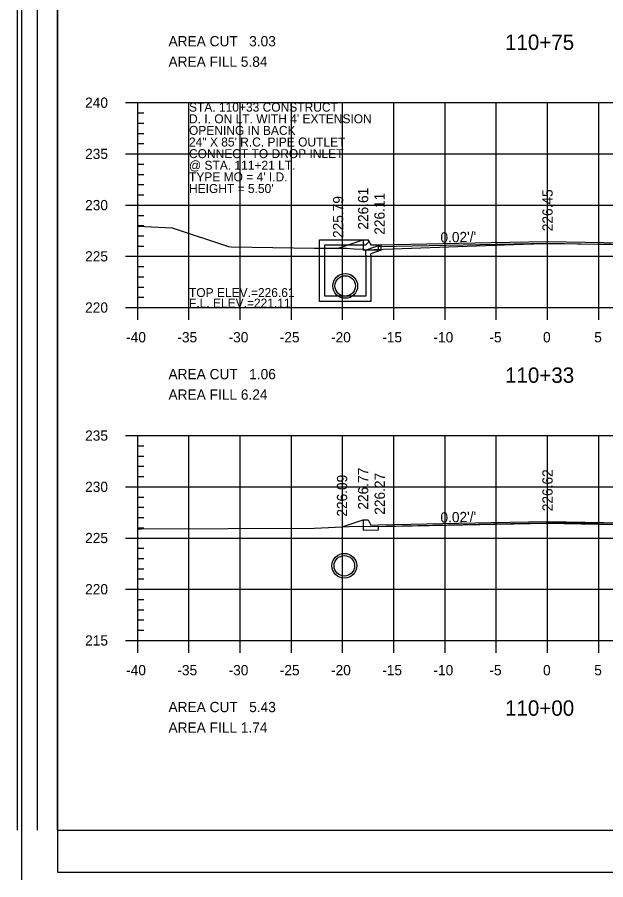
# Model space of a CAD drawing. Extents: x 1367903 to 1373764, y 376865 to 382130.
# Drawn here: x 1372354.5 to 1372469.4, y 377279.1 to 377447.5 of the extents above; entities that cross this region are included whole.
import ezdxf

# ---------------------------------------------------------------- set-up
doc = ezdxf.new("R2010")
doc.units = 0
for name, color, linetype in [('R_Axis', 7, 'Continuous'), ('R_Axis Annot', 7, 'Continuous'), ('R_Border', 7, 'Continuous'), ('R_Border PE', 7, 'Continuous'), ('R_Draft', 7, 'Continuous'), ('R_Exist Surface', 7, 'Continuous'), ('R_Fin Surface', 7, 'Continuous'), ('R_Fin Surface Annot', 7, 'Continuous'), ('R_Grid', 7, 'Continuous'), ('R_Water', 7, 'Continuous'), ('R_Water Annot', 7, 'Continuous')]:
    doc.layers.add(name, color=color, linetype=linetype)

msp = doc.modelspace()

# ---------------------------------------------------------------- linework, layer by layer
for p, q in [((1372413.54, 377404.05), (1372423.04, 377404.05)), ((1372413.54, 377401.05), (1372413.54, 377404.05)), ((1372423.21, 377403.72), (1372423.04, 377404.05)), ((1372414.54, 377401.05), (1372414.54, 377403.05)), ((1372414.54, 377403.05), (1372422.54, 377403.05)), ((1372423.21, 377403.72), (1372422.54, 377403.05)), ((1372425.54, 377403.09), (1372422.54, 377402.05)), ((1372422.54, 377401.05), (1372422.54, 377402.05)), ((1372425.54, 377402.03), (1372423.54, 377401.34)), ((1372423.54, 377401.05), (1372423.54, 377401.34))]:
    msp.add_line(p, q)
for points in [[(1372422.04, 377404.05), (1372422.04, 377403.38), (1372422.04, 377403.38), (1372422.04, 377402.02), (1372425.04, 377402.08), (1372425.04, 377402.74), (1372458.04, 377403.4), (1372491.04, 377402.74), (1372491.04, 377402.08), (1372494.04, 377402.02), (1372494.04, 377403.46), (1372508.04, 377403.74), (1372508.04, 377404.33)], [(1372425.54, 377402.03), (1372425.54, 377403.09)], [(1372422.04, 377349.38), (1372422.04, 377348.71), (1372422.04, 377348.71), (1372422.04, 377347.35), (1372425.04, 377347.41), (1372425.04, 377348.08), (1372458.04, 377348.74), (1372491.04, 377348.08), (1372491.04, 377347.41), (1372494.04, 377347.35), (1372494.04, 377348.79), (1372508.04, 377349.07), (1372508.04, 377349.66)]]:
    msp.add_lwpolyline(points)
at = {"layer": 'R_Axis'}
for p, q in [((1372375.64, 377430.84), (1372380.44, 377430.84)), ((1372378.04, 377390.84), (1372378.04, 377430.84)), ((1372378.04, 377428.84), (1372379.24, 377428.84)), ((1372378.04, 377426.84), (1372379.24, 377426.84)), ((1372378.04, 377424.84), (1372379.24, 377424.84)), ((1372378.04, 377422.84), (1372379.24, 377422.84)), ((1372375.64, 377420.84), (1372380.44, 377420.84)), ((1372378.04, 377418.84), (1372379.24, 377418.84)), ((1372378.04, 377416.84), (1372379.24, 377416.84)), ((1372378.04, 377414.84), (1372379.24, 377414.84)), ((1372378.04, 377412.84), (1372379.24, 377412.84)), ((1372375.64, 377410.84), (1372380.44, 377410.84)), ((1372378.04, 377408.84), (1372379.24, 377408.84)), ((1372378.04, 377406.84), (1372379.24, 377406.84)), ((1372378.04, 377404.84), (1372379.24, 377404.84)), ((1372378.04, 377402.84), (1372379.24, 377402.84)), ((1372375.64, 377400.84), (1372380.44, 377400.84)), ((1372378.04, 377398.84), (1372379.24, 377398.84)), ((1372378.04, 377396.84), (1372379.24, 377396.84)), ((1372378.04, 377394.84), (1372379.24, 377394.84)), ((1372378.04, 377388.44), (1372378.04, 377393.24)), ((1372378.04, 377392.84), (1372379.24, 377392.84)), ((1372388.04, 377388.44), (1372388.04, 377393.24)), ((1372398.04, 377388.44), (1372398.04, 377393.24)), ((1372408.04, 377388.44), (1372408.04, 377393.24)), ((1372418.04, 377388.44), (1372418.04, 377393.24)), ((1372428.04, 377388.44), (1372428.04, 377393.24)), ((1372438.04, 377388.44), (1372438.04, 377393.24)), ((1372448.04, 377388.44), (1372448.04, 377393.24)), ((1372458.04, 377388.44), (1372458.04, 377393.24)), ((1372468.04, 377388.44), (1372468.04, 377393.24)), ((1372375.64, 377390.84), (1372380.44, 377390.84)), ((1372378.04, 377390.84), (1372538.04, 377390.84)), ((1372375.64, 377365.84), (1372380.44, 377365.84)), ((1372378.04, 377325.84), (1372378.04, 377365.84)), ((1372378.04, 377363.84), (1372379.24, 377363.84)), ((1372378.04, 377361.84), (1372379.24, 377361.84)), ((1372378.04, 377359.84), (1372379.24, 377359.84)), ((1372378.04, 377357.84), (1372379.24, 377357.84)), ((1372375.64, 377355.84), (1372380.44, 377355.84)), ((1372378.04, 377353.84), (1372379.24, 377353.84)), ((1372378.04, 377351.84), (1372379.24, 377351.84)), ((1372378.04, 377349.84), (1372379.24, 377349.84)), ((1372378.04, 377347.84), (1372379.24, 377347.84)), ((1372375.64, 377345.84), (1372380.44, 377345.84)), ((1372378.04, 377343.84), (1372379.24, 377343.84)), ((1372378.04, 377341.84), (1372379.24, 377341.84)), ((1372378.04, 377339.84), (1372379.24, 377339.84)), ((1372378.04, 377337.84), (1372379.24, 377337.84)), ((1372375.64, 377335.84), (1372380.44, 377335.84)), ((1372378.04, 377333.84), (1372379.24, 377333.84)), ((1372378.04, 377331.84), (1372379.24, 377331.84)), ((1372378.04, 377329.84), (1372379.24, 377329.84)), ((1372378.04, 377323.44), (1372378.04, 377328.24)), ((1372388.04, 377323.44), (1372388.04, 377328.24)), ((1372398.04, 377323.44), (1372398.04, 377328.24)), ((1372408.04, 377323.44), (1372408.04, 377328.24)), ((1372418.04, 377323.44), (1372418.04, 377328.24)), ((1372428.04, 377323.44), (1372428.04, 377328.24)), ((1372438.04, 377323.44), (1372438.04, 377328.24)), ((1372448.04, 377323.44), (1372448.04, 377328.24)), ((1372458.04, 377323.44), (1372458.04, 377328.24)), ((1372468.04, 377323.44), (1372468.04, 377328.24)), ((1372378.04, 377327.84), (1372379.24, 377327.84)), ((1372375.64, 377325.84), (1372380.44, 377325.84)), ((1372378.04, 377325.84), (1372538.04, 377325.84))]:
    msp.add_line(p, q, dxfattribs=at)
at = {"layer": 'R_Border'}
for p, q in [((1372355.31, 377620.35), (1372355.31, 377279.12)), ((1372362.34, 377611.47), (1372362.34, 377280.59)), ((1372362.34, 377280.59), (1372566.67, 377280.59))]:
    msp.add_line(p, q, dxfattribs=at)
at = {"layer": 'R_Border PE'}
for p, q in [((1372354.51, 377610.76), (1372354.51, 377288.8)), ((1372358.42, 377610.76), (1372358.42, 377288.8)), ((1372362.34, 377288.8), (1372362.34, 377603.25)), ((1372362.34, 377288.8), (1372566.67, 377288.8))]:
    msp.add_line(p, q, dxfattribs=at)
at = {"layer": 'R_Exist Surface'}
for points in [[(1372378.04, 377406.7), (1372384.74, 377406.38), (1372384.83, 377406.37), (1372384.94, 377406.34), (1372395.78, 377402.74), (1372396.26, 377402.72), (1372412.53, 377402.42), (1372418.78, 377402.42), (1372420.3, 377402.28), (1372422.16, 377402.21), (1372422.38, 377402.08), (1372424.2, 377402.18), (1372451.49, 377403.16), (1372457.19, 377403.34), (1372470.55, 377403.2)], [(1372378.04, 377347.64), (1372378.78, 377347.64), (1372412.56, 377347.78), (1372419.33, 377348.07), (1372421.24, 377348.13), (1372423.41, 377348.07), (1372432.75, 377348.31), (1372447.45, 377348.61), (1372457.79, 377348.79), (1372467.68, 377348.79), (1372468.08, 377348.8), (1372488.35, 377348.82), (1372489.19, 377348.8), (1372492.99, 377348.73), (1372494.81, 377348.77), (1372498.58, 377348.74), (1372501.7, 377348.7), (1372524.76, 377348.63), (1372533.92, 377348.34), (1372536.48, 377348.29), (1372538.04, 377348.29)]]:
    msp.add_lwpolyline(points, dxfattribs=at)
at = {"layer": 'R_Fin Surface'}
for points in [[(1372417.16, 377402.42), (1372422.04, 377404.05), (1372423.04, 377404.05), (1372423.54, 377403.05), (1372425.04, 377403.08), (1372447.04, 377403.52), (1372458.04, 377403.74), (1372469.04, 377403.52), (1372491.04, 377403.08), (1372492.54, 377403.05), (1372493.04, 377404.05), (1372494.04, 377404.05), (1372498.04, 377404.13), (1372508.04, 377404.33), (1372509.4, 377403.87)], [(1372417.92, 377348.01), (1372422.04, 377349.38), (1372423.04, 377349.38), (1372423.54, 377348.38), (1372425.04, 377348.41), (1372447.04, 377348.85), (1372458.04, 377349.07), (1372469.04, 377348.85), (1372491.04, 377348.41), (1372492.54, 377348.38), (1372493.04, 377349.38), (1372494.04, 377349.38), (1372498.04, 377349.46), (1372508.04, 377349.66), (1372511, 377348.67)]]:
    msp.add_lwpolyline(points, dxfattribs=at)
at = {"layer": 'R_Grid'}
for p, q in [((1372378.04, 377430.84), (1372538.04, 377430.84)), ((1372378.04, 377390.84), (1372378.04, 377430.84)), ((1372388.04, 377390.84), (1372388.04, 377430.84)), ((1372398.04, 377390.84), (1372398.04, 377430.84)), ((1372408.04, 377390.84), (1372408.04, 377430.84)), ((1372418.04, 377390.84), (1372418.04, 377430.84)), ((1372428.04, 377390.84), (1372428.04, 377430.84)), ((1372438.04, 377390.84), (1372438.04, 377430.84)), ((1372448.04, 377390.84), (1372448.04, 377430.84)), ((1372458.04, 377390.84), (1372458.04, 377430.84)), ((1372468.04, 377390.84), (1372468.04, 377430.84)), ((1372378.04, 377420.84), (1372538.04, 377420.84)), ((1372378.04, 377410.84), (1372538.04, 377410.84)), ((1372378.04, 377400.84), (1372538.04, 377400.84)), ((1372378.04, 377390.84), (1372538.04, 377390.84)), ((1372378.04, 377365.84), (1372538.04, 377365.84)), ((1372378.04, 377325.84), (1372378.04, 377365.84)), ((1372388.04, 377325.84), (1372388.04, 377365.84)), ((1372398.04, 377325.84), (1372398.04, 377365.84)), ((1372408.04, 377325.84), (1372408.04, 377365.84)), ((1372418.04, 377325.84), (1372418.04, 377365.84)), ((1372428.04, 377325.84), (1372428.04, 377365.84)), ((1372438.04, 377325.84), (1372438.04, 377365.84)), ((1372448.04, 377325.84), (1372448.04, 377365.84)), ((1372458.04, 377325.84), (1372458.04, 377365.84)), ((1372468.04, 377325.84), (1372468.04, 377365.84)), ((1372378.04, 377355.84), (1372538.04, 377355.84)), ((1372378.04, 377345.84), (1372538.04, 377345.84)), ((1372378.04, 377335.84), (1372538.04, 377335.84)), ((1372378.04, 377325.84), (1372538.04, 377325.84))]:
    msp.add_line(p, q, dxfattribs=at)
at = {"layer": 'R_Water'}
for p, q in [((1372418.36, 377342.86), (1372418.37, 377342.81)), ((1372418.36, 377342.44), (1372418.37, 377342.4)), ((1372418.36, 377338.44), (1372418.37, 377338.4)), ((1372418.36, 377338.03), (1372418.37, 377337.98))]:
    msp.add_line(p, q, dxfattribs=at)
for points in [[(1372423.54, 377401.05), (1372423.54, 377392.05), (1372418.54, 377392.05), (1372413.54, 377392.05), (1372413.54, 377401.05)], [(1372422.54, 377401.05), (1372422.54, 377393.05), (1372418.54, 377393.05), (1372414.54, 377393.05), (1372414.54, 377401.05)]]:
    msp.add_lwpolyline(points, dxfattribs=at)
for centre, radius in [((1372418.54, 377395.05), 2.42), ((1372418.54, 377395.06), 2.42), ((1372418.54, 377395.06), 2), ((1372418.54, 377395.05), 2), ((1372418.37, 377340.42), 2.42), ((1372418.37, 377340.42), 2)]:
    msp.add_circle(centre, radius, dxfattribs=at)

# ---------------------------------------------------------------- texts
at = {"layer": 'R_Axis Annot'}
for s, height, p in [('AREA CUT   3.03', 2, (1372384.04, 377441.84)), ('110+75', 3, (1372449.75, 377441.14)), ('AREA FILL 5.84', 2, (1372384.04, 377437.84)), ('240', 2, (1372367.76, 377429.84)), ('235', 2, (1372367.76, 377419.84)), ('230', 2, (1372367.76, 377409.84)), ('225', 2, (1372367.76, 377399.84)), ('220', 2, (1372367.76, 377389.84)), ('-40', 2, (1372375.77, 377384.04)), ('-35', 2, (1372385.77, 377384.04)), ('-30', 2, (1372395.77, 377384.04)), ('-25', 2, (1372405.77, 377384.04)), ('-20', 2, (1372415.77, 377384.04)), ('-15', 2, (1372425.77, 377384.04)), ('-10', 2, (1372435.77, 377384.04)), ('-5', 2, (1372446.7, 377384.04)), ('0', 2, (1372457.17, 377384.04)), ('5', 2, (1372467.16, 377384.04)), ('AREA CUT   1.06', 2, (1372384.04, 377376.84)), ('110+33', 3, (1372449.75, 377376.14)), ('AREA FILL 6.24', 2, (1372384.04, 377372.84)), ('235', 2, (1372367.76, 377364.84)), ('230', 2, (1372367.76, 377354.84)), ('225', 2, (1372367.76, 377344.84)), ('220', 2, (1372367.76, 377334.84)), ('215', 2, (1372367.76, 377324.84)), ('-40', 2, (1372375.77, 377319.04)), ('-35', 2, (1372385.77, 377319.04)), ('-30', 2, (1372395.77, 377319.04)), ('-25', 2, (1372405.77, 377319.04)), ('-20', 2, (1372415.77, 377319.04)), ('-15', 2, (1372425.77, 377319.04)), ('-10', 2, (1372435.77, 377319.04)), ('-5', 2, (1372446.7, 377319.04)), ('0', 2, (1372457.17, 377319.04)), ('5', 2, (1372467.16, 377319.04)), ('AREA CUT   5.43', 2, (1372384.04, 377311.84)), ('110+00', 3, (1372449.75, 377311.14)), ('AREA FILL 1.74', 2, (1372384.04, 377307.84))]:
    msp.add_text(s, height=height, dxfattribs=at).set_placement(p)
at = {"layer": 'R_Draft'}
for s, p in [('STA. 110+33 CONSTRUCT', (1372388.04, 377429.09)), ("D. I. ON LT. WITH 4' EXTENSION", (1372388.04, 377426.82)), ('OPENING IN BACK', (1372388.04, 377424.55)), ('24" X 85\' R.C. PIPE OUTLET', (1372388.04, 377422.28)), ('CONNECT TO DROP INLET', (1372388.04, 377420.01)), ('@ STA. 111+21 LT.', (1372388.04, 377417.74)), ("TYPE MO = 4' I.D.", (1372388.04, 377415.47)), ("HEIGHT = 5.50'", (1372388.04, 377413.2))]:
    msp.add_text(s, height=1.75, dxfattribs=at).set_placement(p)
at = {"layer": 'R_Fin Surface Annot'}
for s, rotation, p in [('226.61', 90, (1372423.04, 377406.05)), ('225.79', 90, (1372418.16, 377404.42)), ('226.11', 90, (1372426.25, 377405.05)), ('226.45', 90, (1372459.04, 377405.74)), ("0.02'/'", 1.1455, (1372437.16, 377403.52)), ('226.77', 90, (1372423.04, 377351.38)), ('226.62', 90, (1372459.04, 377351.07)), ('226.09', 90, (1372418.92, 377350.01)), ('226.27', 90, (1372426.28, 377350.38)), ("0.02'/'", 1.1458, (1372437.16, 377348.85))]:
    msp.add_text(s, height=2, rotation=rotation, dxfattribs=at).set_placement(p)
at = {"layer": 'R_Water Annot'}
for s, p in [('TOP ELEV.=226.61', (1372388.04, 377392.89)), ('F.L. ELEV.=221.11', (1372388.04, 377390.84))]:
    msp.add_text(s, height=1.75, dxfattribs=at).set_placement(p)

doc.saveas('drawing.dxf')
